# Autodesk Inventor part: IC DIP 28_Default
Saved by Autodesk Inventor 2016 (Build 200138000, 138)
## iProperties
Created: 2012-01
Part Number: IC DIP 28_Default
Document SubType Name: Modeling
Designer: Trevor
Density: 1 g/cm^3
Material: Generic
Appearance: Default
Author: Trevor
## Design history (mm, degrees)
feature "Base1"
node "Imported1"
